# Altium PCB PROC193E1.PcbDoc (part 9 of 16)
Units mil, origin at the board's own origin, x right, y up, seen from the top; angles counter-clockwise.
Board outline 7700 x 2300 mil, 6 copper layers (Top Layer, GND 1, SIG 1, PWR, GND 2, Bottom Layer), stack 60.98 mil thick; 946 components, 667 nets, 9401 pads, 1730 vias.
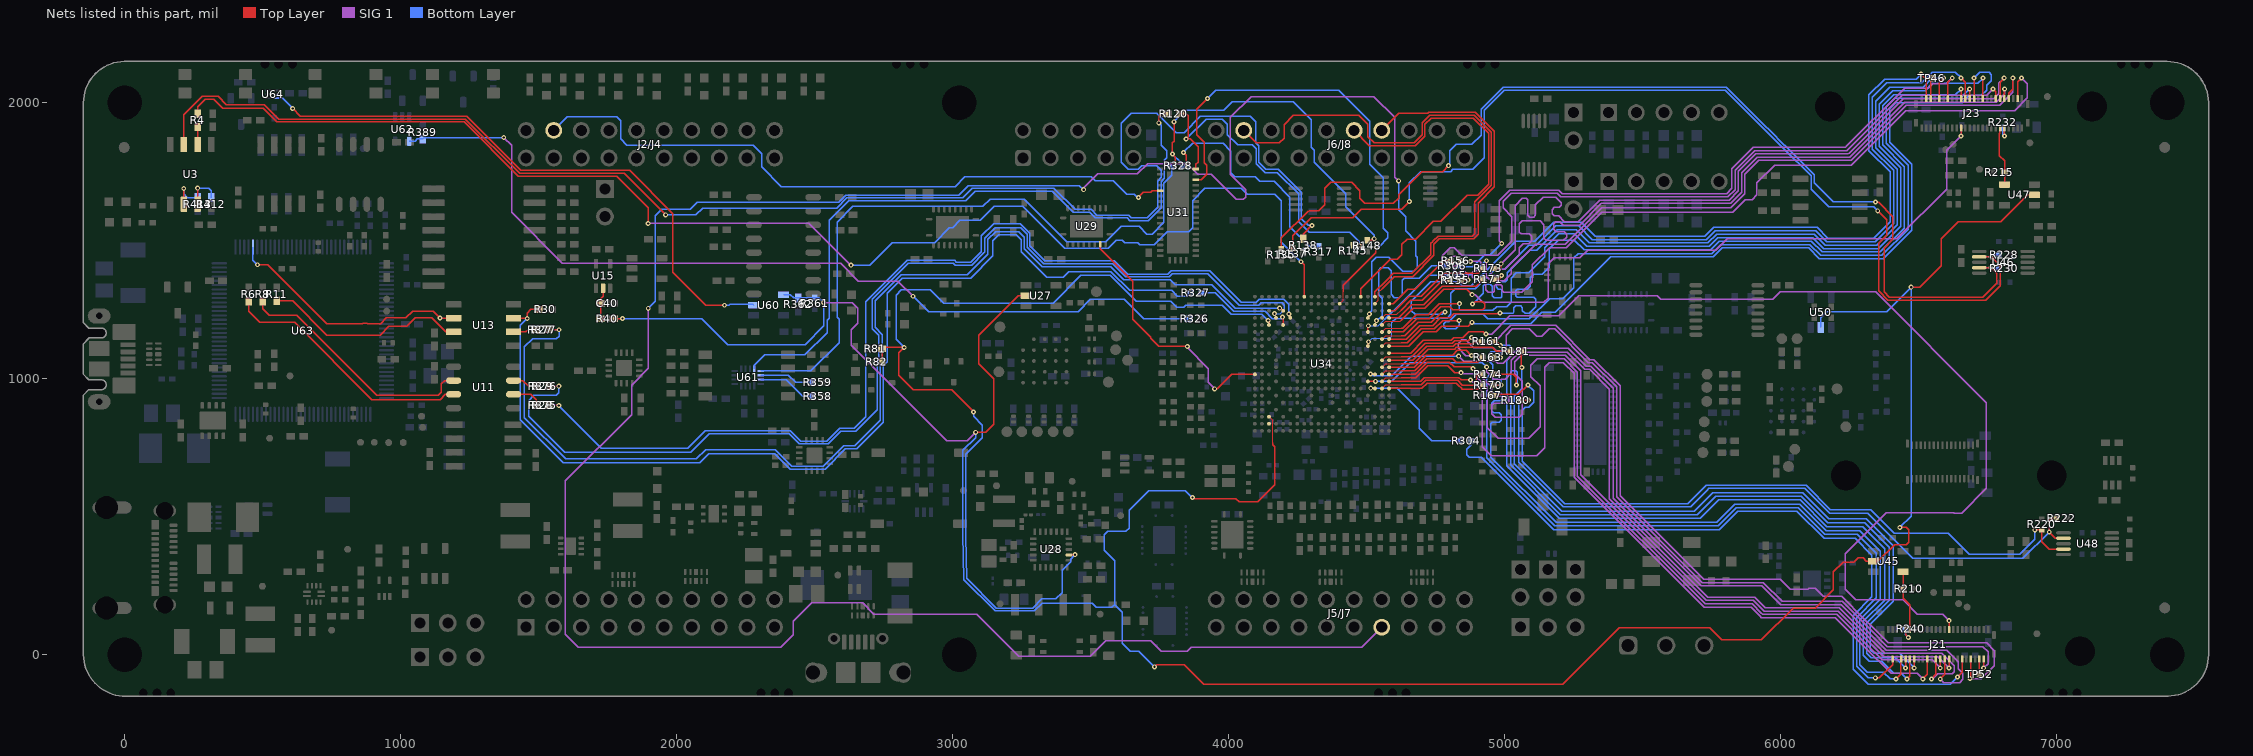
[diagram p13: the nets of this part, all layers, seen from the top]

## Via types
v1: diameter 18, hole 8, Top Layer to Bottom Layer, tented both sides, 1710 vias
v2: diameter 18, hole 8, Top Layer to Bottom Layer, tented top, 12 vias
v3: diameter 23.62, hole 11.81, Top Layer to Bottom Layer, tented both sides, 8 vias

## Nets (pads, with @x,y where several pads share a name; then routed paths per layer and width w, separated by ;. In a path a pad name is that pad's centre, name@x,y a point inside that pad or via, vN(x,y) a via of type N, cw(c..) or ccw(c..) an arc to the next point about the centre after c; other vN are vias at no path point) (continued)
AM261_PORZ: R40.1 R361.1 R362.2 U27.2 U34.V3 U45.2 U47.2 U50.2 U60.4 | length 10447.9
  Top Layer w3.94: U34.V3@4145.67,862.57 4158.46,849.77 4158.46,767.84
  Top Layer w5.3: R40.1@1771.58,1218.35 1802.65,1218.35 v1(1803,1218) ; v1(3082.87,805.99) 3119.32,805.99 3147.88,834.55 3147.88,999.75 3093.76,1053.86 3093.76,1157.29 3237.81,1301.34 U27.2@3265.34,1301.34 ; v1(3730.78,-43.56) 3738.78,-35.56 3837.83,-35.56 3909.6,-107.34 5209.97,-107.34 5415.31,98 5742.28,98 5786.59,53.69 5928.84,53.69 6044.31,169.16 6124.16,169.16 6190.05,235.05 6190.05,300.17 6225.81,335.93 6265.2,335.93 6280.07,350.8 6298.59,350.8 6310.21,339.18 6333.75,339.18 U45.2@6334.74,338.19 6352.07,338.19 6412.1,398.22 6454.99,398.22 6463.84,407.06 6463.84,452.86 6455.3,461.4 v1(6431.32,461.4) ; v1(3868.14,569.65) 3871.57,569.65 3875.52,565.7 4025.57,565.7 4037.48,553.79 4104.58,553.79 4166.63,615.85 4166.63,753.52 4158.46,761.69 4158.46,767.84 ; v1(6472.29,1331.83) 6503.84,1331.83 6581.9,1409.89 6581.9,1507.23 6643.76,1569.08 6797.08,1569.08 6894.33,1666.33 U47.2@6918.85,1666.33
  SIG 1 w4.75: v1(2531.83,1276.32) 2634.87,1276.32 2655.9,1255.29 2655.9,1202.1 2632.03,1178.24 2632.03,1121.49 2977.24,776.28 3053.16,776.28 v1(3082.87,805.99)
  Bottom Layer w5.3: v1(1803,1218) 2090.03,1218 2183.86,1124.17 2464.57,1124.17 2531.83,1191.43 v1(2531.83,1276.32) 2515.11,1293.03 R361.1@2499.12,1293.03 R362.2@2440.55,1293.03 ; U60.4@2386.73,1304.51 2411.53,1304.51 2423.11,1292.92 R362.2@2440.44,1292.92 ; v1(3082.87,805.99) 3082.87,786.59 3036.64,740.36 3036.64,436.49 3039.42,273.9 3039.83,273.5 3039.83,272.38 3153.21,159 3295.57,159 3323.62,187.05 3505.55,187.05 3520.07,172.53 3576.6,172.53 3586.29,182.21 ; v1(3730.78,-43.56) 3674.29,12.92 3673.48,13.74 3668.27,13.74 3643.2,13.74 3614.79,42.15 3614.79,153.71 3586.29,182.21 ; v1(3868.14,569.65) 3842.89,594.9 3709.67,594.9 3639.07,524.3 3639.07,459.27 3627.26,447.45 3561,447.45 3548.77,435.22 3548.77,378.35 3586.29,340.83 3586.29,182.21 ; U50.2@6145.52,1186.5 6145.52,1221.28 6167.38,1243.14 6280.78,1243.14 6383.6,1243.14 v1(6472.29,1331.83) 6472.29,502.36 v1(6431.32,461.4)
AM261_PORZ_PB: U60.2 U64.6 | length 2163.8
  Top Layer w5.3: v1(608.14,1979.7) 636.13,1951.71 1238.29,1951.71 1434.85,1755.15 1828.75,1755.15 1986.19,1597.71 1986.19,1386.39 2105.48,1267.1 2172.34,1267.1 v1(2173.02,1266.42)
  Bottom Layer w5.3: U64.6@551.18,2016.42 571.43,2016.42 v1(608.14,1979.7) ; v1(2173.02,1266.42) 2173.24,1266.65 2189.97,1266.65 2192.62,1269.3 2276.27,1269.3 U60.2@2278.46,1267.1
AM261_PORZ_RC: C40.1 R40.2 U15.2 | length 113.5
  Top Layer w5.3: R40.2@1724.33,1218.35 C40.1@1724.33,1273.35 1724.33,1290.39 1732.95,1299.01 U15.2@1732.95,1328.23
AM261_PR0_MDIO0_MDC: R180.1 R222.1 U48.2 | length 2572.6
  Top Layer w5.3: R180.1@5059.85,922.71 5085.48,922.71 v1(5085.72,922.47) ; R222.1@6997.71,495.49 6982.53,495.49 6972.59,485.56 v1(6972.59,444.64) 6994.75,422.48 7023.87,422.48 U48.2@7024.14,422.21
  Bottom Layer w5.3: v1(5085.72,922.47) 5057.99,922.47 5051.32,915.8 5051.32,697.51 5211.83,537 5674.6,537 5733.53,595.94 5733.53,596.93 5739.72,603.12 6085.95,603.12 6176.94,512.12 6315.27,512.12 6477.87,349.52 6877.48,349.52 v1(6972.59,444.64)
AM261_PR0_MDIO0_MDIO: R167.1 R220.1 U48.4 | length 2715.9
  Top Layer w5.3: R167.1@4957.22,941.07 4959.49,943.34 5049.51,943.34 v1(5083.64,977.48) ; v1(6920.45,451.78) 6920.94,452.27 R220.1@6945.06,452.27 6945.06,410.38 6972.59,382.84 U48.4@7024.14,382.84
  Bottom Layer w5.3: v1(5083.64,977.48) 5105.04,956.08 5105.04,915.26 5087.58,897.8 5074.56,897.8 5063.15,886.39 5063.15,701.47 5216.85,547.77 5663.44,547.77 5729.08,613.42 6091.94,613.42 6179.33,526.02 6325.46,526.02 6411.47,440.02 6606.22,440.02 6682.67,363.56 6864.98,363.56 6920.45,419.03 v1(6920.45,451.78)
AM261_PR1_MDIO0_MDC: R135.1 R230.1 U46.9 | length 3758.4
  Top Layer w5.3: R135.1@4190.71,1469.03 4190.71,1510.97 4287.64,1607.9 4290.7,1607.9 4291.26,1608.46 4297.13,1608.46 4297.23,1608.35 4313.4,1608.35 4313.51,1608.46 4325.99,1608.46 4348.04,1630.51 4348.04,1690.69 4368.59,1711.25 4444.8,1711.25 4474.68,1681.36 4474.68,1653.59 4493.01,1635.26 4595.87,1635.26 4615.01,1654.4 4615.01,1666.72 4699.18,1750.9 4774.65,1750.9 v1(4795.88,1772.13) ; v1(6343,1641) 6344.82,1639.18 6354.55,1639.18 6406,1587.74 6406,1504.81 6374.02,1472.83 6374.02,1315.35 6393.44,1295.93 6731.9,1295.93 6782.48,1346.51 6782.48,1382.23 v1(6761.95,1402.77) 6761.71,1402.53 U46.9@6719.18,1402.53
  Bottom Layer w5.3: v1(4795.88,1772.13) 4795.88,1775.57 4801.18,1780.86 4801.18,1826.01 4824.54,1849.38 4880.6,1849.38 4914.01,1882.8 4914.01,1976.18 4993.59,2055.76 5803.18,2055.76 5941.68,1917.26 5941.68,1917.13 5959.15,1899.66 5959.27,1899.66 6013.01,1845.92 6013.85,1845.92 6121.02,1738.75 6121.02,1709.71 6189.73,1641 v1(6343,1641) ; v1(6761.95,1402.77) 6764.39,1400.32 R230.1@6789.85,1400.32
AM261_PR1_MDIO0_MDIO: R137.1 R228.1 U46.7 | length 3715.2
  Top Layer w5.3: R137.1@4231.93,1473.63 4231.93,1517.49 4298.13,1583.7 4449.26,1583.7 4450.38,1584.81 4450.74,1584.81 4480.49,1614.56 4626.38,1614.56 v1(4654.17,1642.35) ; v1(6351.26,1608.66) 6383.48,1576.43 6383.48,1520.4 6354,1490.92 6354,1318.76 6387.43,1285.33 6743.24,1285.33 6795.1,1337.2 6795.1,1408.75 v1(6761.95,1441.9) U46.7@6719.18,1441.9
  Bottom Layer w5.3: v1(4654.17,1642.35) 4654.17,1709.91 4695.07,1750.81 4804.37,1750.81 4811.99,1758.43 4883.27,1758.43 4925.07,1800.23 4925.07,1972.24 4998.29,2045.46 5798.91,2045.46 5931.38,1912.99 5931.38,1912.87 5954.88,1889.36 5955.01,1889.36 6008.75,1835.62 6009.58,1835.62 6110.42,1734.78 6110.42,1686.81 6174.33,1622.91 6337.01,1622.91 v1(6351.26,1608.66) ; v1(6761.95,1441.9) 6768.79,1448.74 R228.1@6789.85,1448.74
AM261_RESETN_PB: R326.1 R389.1 U62.4 | length 3280
  SIG 1 w4.75: v1(1373,1874) 1401.47,1845.53 1401.47,1602.53 1585.46,1418.54 2593.61,1418.54 2658.32,1353.82 2801.38,1353.82 v1(2856.14,1299.07)
  Bottom Layer w5.3: U62.4@1030.59,1860.75 1052.07,1860.75 1060.28,1868.97 R389.1@1079.41,1868.97 1084.44,1874 v1(1373,1874) ; v1(2856.14,1299.07) 2896.75,1258.45 2912.45,1242.76 3453.97,1242.76 3498.78,1287.58 3621.16,1287.58 3691.51,1217.23 R326.1@3853.59,1217.23
AM261_RGMII1_INTn: J23.10 R232.1 | length 61.5
  Top Layer w5.3: v1(6810.42,1879.92) J23.10@6810.42,1908.44
  Bottom Layer w5.3: R232.1@6804.23,1910.3 6804.23,1886.1 v1(6810.42,1879.92)
AM261_RGMII1_RD0: J23.23 U34.H20 | length 3170.8
  Top Layer w5.3: U34.H20@4580.71,1118.47 4652.87,1118.47 4705.4,1170.99 4751.53,1170.99 4771.29,1190.76 4867.08,1190.76 v1(4881.08,1204.76) ; v1@6699.81,2089.31 6700.18,2088.94 J23.23@6700.18,2015.13
  Bottom Layer w5.3: v1(4881.08,1204.76) 4884.35,1204.76 4889.33,1199.78 5094,1199.78 5134.71,1240.49 5182.49,1240.49 5383.33,1441.33 5754.9,1441.33 5787.66,1474.09 6100.52,1474.09 6139.91,1434.7 6261.94,1434.7 6261.99,1434.65 6370.97,1434.65 6473.68,1537.35 6473.68,1778.03 6393.86,1857.85 6393.86,1979.1 6415.8,2001.04 6658.02,2001.04 6683.51,2026.54 6726.76,2026.54 6746.24,2046.02 6746.24,2062.97 6763.05,2079.78 6763.05,2102.24 6755.25,2110.04 6720.55,2110.04 v1@6699.81,2089.31
  other v1: 6699.81,2090
AM261_RGMII1_RD1: J23.25 U34.H19 | length 3184.2
  Top Layer w3.94: U34.H19@4555.12,1118.47 4567.91,1131.27 4624.25,1131.27
  Top Layer w5.3: 4624.25,1131.27 4647.16,1131.27 4697.48,1181.59 4745.06,1181.59 4774.3,1210.83 v1(4834.81,1210.83) ; J23.25@6684.43,2015.13 v1(6684.43,2050.04)
  Bottom Layer w5.3: v1(4834.81,1210.83) 4834.81,1193.96 4822.3,1181.45 4786.06,1181.45 4779,1188.5 4779,1200 4785.39,1206.39 4797.39,1206.39 4824.43,1233.43 4921.52,1233.43 4938.1,1216.85 5089.47,1216.85 5163.09,1290.46 5210.21,1290.46 5250.49,1330.75 5250.49,1438.49 5265.76,1453.76 5749.75,1453.76 5782.51,1486.51 6105.67,1486.51 6145.05,1447.12 6267.08,1447.12 6267.14,1447.07 6365.83,1447.07 6461.26,1542.5 6461.26,1772.89 6381.44,1852.71 6381.44,1984.78 6412.42,2015.77 6650.16,2015.77 v1(6684.43,2050.04)
AM261_RGMII1_RD2: J23.27 U34.H17 | length 3183.6
  Top Layer w5.3: U34.H17@4503.93,1118.47 4503.93,1132.35 v1(4505.78,1134.2) ; v1(6653,2090) 6668.69,2074.32 J23.27@6668.69,2015.13
  Bottom Layer w3.94: v1(4505.78,1134.2) 4519.01,1147.43 4584.02,1147.43 4591.3,1154.71 4591.3,1205.37
  Bottom Layer w5.3: 4591.3,1205.37 4605.99,1220.06 4791.38,1220.06 4804.75,1233.43 4804.75,1310.46 4819.72,1325.44 4892.1,1325.44 4962.91,1396.25 4999.25,1396.25 5086.24,1483.24 5114.24,1483.24 5184.93,1553.93 5268.07,1553.93 5317.38,1504.62 5730.33,1504.62 5761.92,1536.21 6126.25,1536.21 6165.64,1496.82 6342.34,1496.82 6408.94,1563.43 6408.94,1754.91 6331.74,1832.12 6331.74,2020.32 6383.69,2072.27 6510,2072.27 6548.92,2111.2 6631.8,2111.2 v1(6653,2090)
AM261_RGMII1_RD3: J23.29 U34.G20 | length 3183.5
  Top Layer w5.3: U34.G20@4580.71,1144.06 4642.99,1144.06 4692.01,1193.07 4739.02,1193.07 4766.95,1221.01 4769.91,1221.01 4770.04,1221.13 4801.64,1221.13 4815.41,1234.91 4972.93,1234.91 4973.55,1235.53 4979.95,1235.53 v1(4982.38,1237.96) ; J23.29@6652.94,2015.13 v1(6652.94,2050.04)
  Bottom Layer w5.3: v1(4982.38,1237.96) 4982.53,1237.81 5029.9,1237.81 5033,1240.91 5033,1258.06 5039.01,1264.08 5057.23,1264.08 5064,1257.31 5064,1247.18 5074.2,1236.98 5088.92,1236.98 5113,1261.06 5113,1287.69 5104.69,1296 5045,1296 5040.01,1300.99 5040.01,1318.65 5045.91,1324.54 5080.54,1324.54 5091.53,1335.53 5091.53,1366.53 5104,1379 5136,1379 5161.9,1404.9 5161.9,1471.9 5192.81,1502.81 5251.79,1502.81 5287.25,1467.35 5492.87,1467.35 5745.77,1467.35 5777.36,1498.94 6110.81,1498.94 6150.2,1459.55 6272.23,1459.55 6272.29,1459.5 6360.68,1459.5 6447.48,1546.29 6447.48,1769.09 6369.01,1847.56 6369.01,1989.93 6408.35,2029.27 6632.75,2029.27 6652.94,2049.45 v1(6652.94,2050.04)
AM261_RGMII1_RESETn: J23.12 R215.1 U47.4 | length 213.7
  Top Layer w5.3: J23.12@6794.67,1908.44 6793.97,1907.75 6793.97,1889.85 6791.77,1887.65 6791.77,1872.2 6791.96,1872.01 6791.96,1807.8 6810.6,1789.16 R215.1@6810.6,1749.22 U47.4@6810.6,1703.75
AM261_RGMII1_RX_CTL: J23.45 U34.G19 | length 3183.5
  Top Layer w3.94: U34.G19@4555.12,1144.06 4567.91,1156.86 4624.25,1156.86
  Top Layer w5.3: 4624.25,1156.86 4638.25,1156.86 4686.57,1205.18 4734.35,1205.18 4770.68,1241.52 v1(4783.61,1241.52) ; v1(6508.62,2104.04) 6526.95,2085.71 J23.45@6526.95,2015.13
  Bottom Layer w5.3: v1(4783.61,1241.52) 4781.92,1241.52 4774.16,1233.75 4674.89,1233.75 4661.86,1246.79 4661.86,1281.83 4732.02,1352 4831,1352 4845.02,1337.98 4878.98,1337.98 5040,1499 5108.98,1499 5177.98,1568 5276.13,1568 5327,1517.13 5725.26,1517.13 5756.78,1548.64 6131.4,1548.64 6170.79,1509.25 6337.19,1509.25 6396.52,1568.58 6396.52,1749.77 6319.31,1826.97 6319.31,2029.11 6376.2,2086 6490.59,2086 v1(6508.62,2104.04)
AM261_RGMII1_RXC: J23.19 U34.F19 | length 3173.7
  Top Layer w3.94: U34.F19@4555.12,1169.65 4567.91,1182.45 4624.25,1182.45
  Top Layer w5.3: 4624.25,1182.45 4630.49,1182.45 4679.86,1231.82 4722.18,1231.82 4762.38,1272.01 v1(4835.37,1272.01) ; J23.19@6731.68,2015.13 6731.68,2088.05 v1@6732.91,2089.29
  Bottom Layer w5.3: v1(4835.37,1272.01) 4835.37,1250.98 4838.47,1247.88 4956.88,1247.88 4970.21,1261.21 5006.69,1261.21 5022.54,1277.06 5022.54,1364.54 5041.82,1383.82 5086.04,1383.82 5145,1442.79 5145,1475 5195,1525 5252,1525 5297.23,1479.77 5487.72,1479.77 5740.62,1479.77 5772.22,1511.36 6115.96,1511.36 6155.35,1471.97 6277.38,1471.97 6277.43,1471.92 6352.57,1471.92 6433.79,1553.14 6433.79,1765.21 6356.59,1842.41 6356.59,1995.08 6405.51,2044 6522.97,2044 6549.08,2070.11 6713.74,2070.11 v1@6732.67,2089.05
  other v1: 6732.91,2090
AM261_RGMII1_RXLINK: J23.43 TP46.1 | length 75.9
  Top Layer w5.3: J23.43@6542.7,2015.13 6542.7,2084.44 TP46.1@6547.36,2089.1
AM261_RGMII1_TD0: J23.7 R305.1 | length 2564.5
  Top Layer w5.3: J23.7@6826.17,2015.13 6826.17,2035.17 6840.77,2049.77 v1(6840.77,2089.76)
  SIG 1 w4.75: v1(4933.45,1427.73) 4933.45,1370.66 4949.53,1354.58 4997.8,1354.58 5024.13,1380.92 5024.13,1400.13 5112,1488 5218.57,1488 5350.4,1619.83 5819.08,1619.83 5869.88,1670.62 5869.88,1741.3 5919.85,1791.28 6254.49,1791.28 6257.5,1794.29 6434.39,1971.19 6453.98,1990.77 6792.75,1990.77 6840.77,2038.8 v1(6840.77,2089.76)
  Bottom Layer w5.3: R305.1@4829.77,1374.48 4832.81,1377.52 4879.17,1377.52 4924.73,1423.09 4925.37,1423.09 4930.02,1427.73 v1(4933.45,1427.73)
AM261_RGMII1_TD0_R: R305.2 U34.F17 | length 383.6
  Top Layer w5.3: U34.F17@4503.93,1169.65 4503.93,1190.6 v1(4505.56,1192.22)
  Bottom Layer w3.94: v1(4505.56,1192.22) 4542.22,1192.22 4565.5,1215.5
  Bottom Layer w5.3: 4565.5,1215.5 4624.25,1274.25 4724.48,1374.48 R305.2@4790.4,1374.48
AM261_RGMII1_TD1: J23.9 R171.1 | length 2655.9
  Top Layer w5.3: R171.1@4959.95,1359.91 4978.3,1359.91 4987.57,1369.18 v1(4987.57,1374.48) ; J23.9@6810.42,2015.13 6810.42,2049.35 v1(6811.11,2050.04)
  SIG 1 w4.75: v1(4987.57,1374.48) 4956.52,1374.48 4950.64,1380.36 4950.64,1397.67 4956.14,1403.16 4969.84,1403.16 4975.5,1397.5 5000.5,1397.5 5053,1450 5053,1475.23 5066.77,1489 5087,1489 5098,1500 5098,1516 5089,1525 5059,1525 5053,1531 5053,1562 5063,1572 5128.99,1572 5142,1558.99 5142,1509.22 5150.05,1501.17 5211.89,1501.17 5224.31,1513.59 5224.31,1524.2 5216.03,1532.48 5187.16,1532.48 5178,1541.64 5178,1561.52 5185.18,1568.7 5199.3,1568.7 5211,1557 5270.78,1557 5348.5,1634.72 5348.88,1634.72 5349.45,1635.29 5386.85,1635.29 5450.61,1635.29 5817.75,1635.29 5858,1675.54 5858,1746.22 5914.93,1803.15 5955.99,1803.15 6249.57,1803.15 6252.58,1806.17 6434.39,1987.98 6449.06,2002.65 6781.02,2002.65 6811.11,2032.74 v1(6811.11,2050.04)
AM261_RGMII1_TD1_R: R171.2 U34.D20 | length 397.5
  Top Layer w5.3: U34.D20@4580.71,1220.83 4615.38,1220.83 4663.43,1268.88 4706.62,1268.88 4773.27,1335.52 4896.19,1335.52 R171.2@4920.58,1359.91
AM261_RGMII1_TD2: J23.11 R173.1 | length 2644.3
  Top Layer w5.3: R173.1@4960.18,1399.64 4979.94,1399.64 4986.77,1406.46 v1(4986.77,1416.83) ; J23.11@6794.67,2015.13 6794.67,2075.16 v1(6809.27,2089.76)
  SIG 1 w4.75: v1(4986.77,1416.83) 5037.71,1467.78 5037.71,1627.44 5063.84,1653.57 5078.04,1653.57 5083,1648.61 5083,1592.99 5089.99,1586 5104.32,1586 5111.19,1592.87 5111.19,1630.42 5138.94,1658.17 5185.06,1658.17 5204.84,1638.39 5204.84,1628.63 5196.93,1620.71 5179.84,1620.71 5171.1,1611.97 5171.1,1598.1 5179.19,1590 5195,1590 5215.67,1569.33 5266.31,1569.33 5343.58,1646.6 5343.96,1646.6 5344.53,1647.17 5381.93,1647.17 5455.53,1647.17 5812.83,1647.17 5846.13,1680.46 5846.13,1751.14 5910.01,1815.03 5960.91,1815.03 6244.65,1815.03 6247.66,1818.04 6434.39,2004.77 6444.14,2014.52 6771.86,2014.52 6789.89,2032.55 6789.89,2070.38 v1(6809.27,2089.76)
AM261_RGMII1_TD2_R: R173.2 U34.C20 | length 403.6
  Top Layer w5.3: U34.C20@4580.71,1246.42 4600.65,1246.42 4653.73,1299.5 4697.98,1299.5 4780.33,1381.85 4903.03,1381.85 R173.2@4920.81,1399.64
AM261_RGMII1_TD3: J23.13 R155.1 | length 2740.9
  Top Layer w5.3: R155.1@4839.51,1357.29 4866.29,1357.29 v1(4867,1358) ; v1(6769.25,2050.35) 6778.92,2040.68 J23.13@6778.92,2015.13
  SIG 1 w4.75: v1(4867,1358) 4866.88,1358.12 4866.88,1376.82 4850.23,1393.47 4841.12,1393.47 4832.34,1384.69 4823.51,1384.69 4813.05,1395.15 4813.05,1402.05 4834.04,1423.04 4834.04,1433 4823.04,1444 4812,1444 4793.04,1425.04 4782.04,1425.04 4773.57,1433.51 4773.57,1446.65 4802.14,1475.22 4816.78,1475.22 4844.67,1447.33 4974.06,1447.33 5025.83,1499.11 5025.83,1587.8 4994.06,1619.58 4994.06,1643.06 5023,1672 5190,1672 5202.96,1659.04 5377.01,1659.04 5460.45,1659.04 5807.91,1659.04 5834.25,1685.38 5834.25,1756.06 5905.09,1826.9 5965.83,1826.9 6239.73,1826.9 6242.75,1829.92 6434.39,2021.57 6439.28,2026.46 6745.35,2026.46 v1(6769.25,2050.35)
AM261_RGMII1_TD3_R: R155.2 U34.D19 | length 301.5
  Top Layer w3.94: U34.D19@4555.12,1220.83 4567.91,1233.63 4608.63,1233.63 4624.25,1249.25
  Top Layer w5.3: 4624.25,1249.25 4659.88,1284.88 4700.37,1284.88 4772.78,1357.29 R155.2@4800.14,1357.29
AM261_RGMII1_TX_CTL: J23.35 R306.1 | length 2312.8
  Top Layer w5.3: J23.35@6605.69,2015.13 6605.69,2074.01 v1@6621.15,2089.47
  SIG 1 w4.75: v1(4988.9,1490.44) 4988.9,1490.91 4979.96,1499.85 4979.96,1645.96 5018,1684 5141.8,1684 5141.92,1683.88 5194.92,1683.88 5207.58,1671.21 5803.29,1671.21 5822.38,1690.3 5822.38,1760.98 5900.18,1838.78 5970.75,1838.78 6234.81,1838.78 6237.83,1841.79 6434.39,2038.36 6449.06,2053.03 6534.34,2053.03 6550.48,2069.16 6600.31,2069.16 v1(6621.15,2090)
  Bottom Layer w5.3: R306.1@4829.77,1409.48 4833.49,1405.76 4883.87,1405.76 4926.71,1448.6 4947.06,1448.6 v1(4988.9,1490.44)
AM261_RGMII1_TX_CTL_R: R306.2 U34.E18 | length 637.7
  Top Layer w5.3: U34.E18@4529.52,1195.24 v1(4535.54,1210.46)
  Bottom Layer w5.3: v1(4535.54,1210.46) 4536.71,1210.46 4555.31,1229.06 4555.31,1291.11 4542.42,1304 4542.42,1348.43 4542.42,1393.32 4550.68,1401.59 4578.41,1401.59 4588,1392 4588,1305.91 4599.91,1294 4617,1294 4628,1305 4628,1356.28 4635.72,1364 4690.25,1364 4735.73,1409.48 R306.2@4790.4,1409.48
AM261_RGMII1_TXC: J23.3 R156.1 | length 2766.3
  Top Layer w5.3: R156.1@4842.45,1428.43 4872.07,1428.43 v1(4875.21,1425.28) ; J23.3@6857.87,2015.34 6857.87,2075.37 6858.2,2075.7 v1(6872.26,2089.76)
  SIG 1 w4.75: v1(4875.21,1425.28) 4908.72,1425.28 4916.87,1417.13 4916.87,1397.58 4910.28,1391 4889.23,1391 4882.63,1384.4 4882.63,1370.52 4890,1363.16 4922.4,1363.16 4930.75,1354.81 4930.75,1322.41 4940.38,1312.78 4957.78,1312.78 4962,1317 4962,1336.27 4967.12,1341.39 4985.55,1341.39 4991,1335.93 4991,1318.43 4996.65,1312.78 5061.41,1312.78 5099.98,1351.35 5099.98,1412.89 5162.09,1475 5222.36,1475 5350.73,1603.37 5825.42,1603.37 5870.71,1648.65 5896.33,1648.65 5913.75,1666.08 5913.75,1710.9 5977.31,1774.46 6255.02,1774.46 6434.39,1953.84 6452.6,1972.04 6847.52,1972.04 6893.12,2017.64 6893.12,2068.91 v1(6872.26,2089.76)
AM261_RGMII1_TXC_R: R156.2 U34.B20 | length 287.2
  Top Layer w5.3: U34.B20@4580.71,1272.01 4596.26,1272.01 4648.73,1324.48 4674.86,1324.48 4778.81,1428.43 R156.2@4803.08,1428.43
AM261_RGMII2_INTn: J21.10 R240.1 | length 68.9
  Top Layer w5.3: J21.10@6452.05,91.39 6452.05,73 v1(6462.05,63)
  Bottom Layer w5.3: R240.1@6451.15,94.86 6451.15,73.9 v1(6462.05,63)
AM261_RGMII2_RD0: J21.23 U34.N17 | length 3150.9
  Top Layer w5.3: U34.N17@4503.93,990.52 4504.19,990.77 4531.32,990.77 v1(4531.57,991.02) ; v1@6546.18,-86.1 6561.9,-70.38 6561.9,-15.69 J21.23@6562.29,-15.3
  SIG 1 w4.75: v1(4934.45,1042.98) 4934.45,1024.8 4960.26,999 5001.15,999 5024.24,1022.09 5024.24,1067.19 5054.06,1097 5227.13,1097 5289.85,1034.28 5307.34,1034.28 5379,962.62 5379,565.07 5734.92,209.16 5905.08,209.16 5944.35,169.88 6212.56,169.88 6213.51,168.93 6317.96,64.49 6377.22,5.23 6583.55,5.23 6628.45,-39.66 6628.45,-61.49 6621.99,-67.94 6569.01,-67.94 6549.76,-87.19 v1(6546.18,-87.19)
  Bottom Layer w5.3: v1(4531.57,991.02) 4590.16,991.02 4657.6,1058.47 4918.96,1058.47 v1(4934.45,1042.98)
AM261_RGMII2_RD1: J21.25 U34.N19 | length 3255.1
  Top Layer w3.94: U34.N19@4555.12,990.52 4567.91,1003.31 4623.54,1003.31 4623.63,1003.22 4624.25,1003.22
  Top Layer w5.3: 4624.25,1003.22 4676.63,1003.22 4719.99,1046.58 4793.42,1046.58 4817.89,1022.11 v1(4841.82,1022.11) ; v1@6578.04,-47.3 J21.25@6578.04,-15.3
  Top Layer w8: v1(6577.7,-47.64) v1@6578.04,-47.3
  SIG 1 w4.75: v1(4841.82,1022.11) 4845.41,1022.11 4849.36,1018.16 4885.84,1018.16 4937,967 4937,823 4976,784 5086,784 5127.83,825.83 5127.83,974.35 5094,1008.18 5094,1049.71 5117,1072.71 5214.94,1072.71 5263.07,1024.58 5263.07,647.42 5726.28,184.2 5896.45,184.2 5929.79,150.86 5934.52,146.13 5984.69,146.13 6202.72,146.13 6203.68,145.18 6308.12,40.74 6367.38,-18.52 6548.59,-18.52 v1(6577.7,-47.64)
AM261_RGMII2_RD2: J21.27 U34.M18 | length 3156.1
  Top Layer w5.3: v1(4513.35,1017.16) 4513.87,1016.63 4529,1016.63 U34.M18@4529.52,1016.11 ; v1@6577.67,-86.1 6593.33,-70.44 6593.33,-54.13 ; 6593.35,-54.12 6593.35,-41.15 6593.33,-15.75 J21.27@6593.79,-15.3
  SIG 1 w4.75: v1(4833,1082) 4850.92,1064.08 4966.97,1064.08 4974.74,1056.3 4994.73,1056.3 5048.7,1110.28 5230.65,1110.28 5294.77,1046.16 5312.25,1046.16 5392.96,965.46 5392.96,567.91 5711.37,249.5 5931.71,249.5 5999.45,181.76 6217.48,181.76 6218.43,180.81 6322.88,76.36 6382.13,17.1 6601.9,17.1 6643.28,-24.28 6643.28,-50.22 6659.97,-66.91 6659.97,-89.47 6648.73,-100.72 6591.2,-100.72 v1(6577.67,-87.19)
  Bottom Layer w5.3: v1(4513.35,1017.16) 4516.79,1017.16 4522.49,1011.45 4589.85,1011.45 4660.4,1082 v1(4833,1082)
AM261_RGMII2_RD3: J21.29 U34.M20 | length 3256.6
  Top Layer w5.3: U34.M20@4580.71,1016.11 4674.95,1016.11 4719.31,1060.47 4799.58,1060.47 4816.82,1043.23 4876.04,1043.23 4881.54,1037.73 v1(4884.98,1037.73) ; v1@6609.53,-47.3 J21.29@6609.53,-15.3
  Top Layer w8: v1(6609.2,-47.64) v1@6609.53,-47.3
  SIG 1 w4.75: v1(4884.98,1037.73) 4953,969.71 4953,946 4963,936 5010,936 5015,931 5015,917 5009,911 4960,911 4953,904 4953,873 4965,861 5052,861 5063,872 5063,991.22 5036.76,1017.47 5036.76,1061.1 5060.24,1084.58 5219.86,1084.58 5274.94,1029.5 5274.94,652.34 5730.32,196.96 5900.49,196.96 5934.71,162.74 5939.43,158.01 5989.61,158.01 6207.64,158.01 6208.6,157.06 6313.04,52.61 6372.3,-6.65 6568.21,-6.65 v1(6609.2,-47.64)
AM261_RGMII2_RESETn: J21.12 R210.1 U45.4 | length 219.7
  Top Layer w5.3: U45.4@6443,300.79 R210.1@6443,239.5 6443,205.39 6467.8,180.59 J21.12@6467.8,91.39
AM261_RGMII2_RX_CTL: J21.45 U34.L20 | length 3243.5
  Top Layer w5.3: U34.L20@4580.71,1041.7 4671.41,1041.7 4715.61,1085.9 4810.52,1085.9 4827.35,1102.72 4860.44,1102.72 v1(4878.89,1084.27) ; v1@6735.52,-47.3 J21.45@6735.52,-15.3
  Top Layer w8: v1(6735.18,-47.64) v1@6735.52,-47.3
  SIG 1 w4.75: v1(4878.89,1084.27) 4859.07,1084.27 4831.1,1112.25 4831.1,1127.09 4844.88,1140.88 4858.88,1140.88 4887.75,1112 4958.48,1112 4969,1101.48 4992.49,1101.48 5004.51,1113.49 5004.51,1158.43 5026.62,1180.54 5088.73,1180.54 5115.25,1154.03 5134.32,1154.03 5160.8,1180.51 5180.26,1180.51 5302.73,1058.03 5317.17,1058.03 5404.83,970.38 5404.83,572.83 5716.29,261.37 5936.63,261.37 6004.37,193.63 6222.4,193.63 6327.79,88.24 6386.24,29.79 6732.43,29.79 6751.11,11.11 6751.11,-31.71 v1(6735.18,-47.64)
AM261_RGMII2_RXC: J21.19 U34.N20 | length 3257.6
  Top Layer w5.3: U34.N20@4580.71,990.52 4694.85,990.52 4709.03,1004.7 4833.15,1004.7 4841.71,996.14 v1(4876.25,996.14) ; v1@6514.68,-86.1 6530.4,-70.39 6530.4,-15.7 J21.19@6530.79,-15.3
  SIG 1 w4.75: v1(4876.25,996.14) 4918.3,954.09 4918.3,754.7 4951,722 5116,722 5144,750 5144,1041.98 5161.04,1059.02 5211.84,1059.02 5251.19,1019.66 5251.19,642.5 5721.89,171.81 5892.05,171.81 5924.87,138.99 5929.6,134.26 5979.77,134.26 6197.8,134.26 6303.2,28.86 6399.74,-67.68 6495.17,-67.68 v1(6514.68,-87.19)
AM261_RGMII2_RXLINK: J21.43 TP52.1 | length 54.1
  Top Layer w5.3: TP52.1@6719.47,-69.7 J21.43@6719.47,-15.6
AM261_RGMII2_TD0: J21.7 R170.1 | length 2754.3
  Top Layer w5.3: R170.1@4959.55,977.47 4986.77,977.47 v1(4986.85,977.38) ; v1(6417.81,-87.19) 6434.92,-70.09 6434.92,-16.69 J21.7@6436.31,-15.3
  Bottom Layer w5.3: v1(4986.85,977.38) 4986.85,991.15 4979.49,998.51 4959.19,998.51 4949.66,988.99 4949.66,957.34 4957,950 4982.81,950 4990,942.81 4990,926 4984,920 4961.48,920 4953.5,912.02 4953.5,882.81 4959.31,877 4979.54,877 4987,869.54 4987,849.61 4980.39,843 4954.66,843 4949.66,838 4949.66,715.98 5185.63,480.02 5768.81,480.02 5833.99,545.19 6068.67,545.19 6164.24,449.62 6286.04,449.62 6360.81,374.85 6360.81,201.06 6286.84,127.09 6286.84,-35.83 6313.43,-62.43 6370.89,-62.43 6395.65,-87.19 v1(6417.81,-87.19)
AM261_RGMII2_TD0_R: R170.2 U34.P20 | length 362.6
  Top Layer w5.3: U34.P20@4580.71,964.93 4699.68,964.93 4718.85,984.1 4824.62,984.1 4833.47,975.25 4841.53,967.19 4841.81,967.19 4846.5,962.51 4905.23,962.51 R170.2@4920.18,977.47
AM261_RGMII2_TD1: J21.9 R174.1 | length 2689.8
  Top Layer w5.3: R174.1@4960.18,1015.72 5031.28,1015.72 5041.94,1005.06 v1(5041.94,977.15) ; v1@6452.05,-47.3 J21.9@6452.05,-15.3
  Top Layer w8: v1(6451.72,-47.64) v1@6452.05,-47.3
  Bottom Layer w5.3: v1(5041.94,977.15) 5044.37,979.58 5044.37,1023.63 5039.02,1028.98 5025.98,1028.98 5020.95,1023.95 5020.95,687.82 5201.28,507.5 5691.09,507.5 5691.25,507.66 5696.72,507.66 5751.46,562.4 5751.56,562.4 5763.95,574.79 6074.22,574.79 6169.75,479.26 6303.5,479.26 6393.36,389.39 6393.36,197.5 6311.69,115.83 6311.69,4.92 6327.15,-10.54 6414.62,-10.54 v1(6451.72,-47.64)
AM261_RGMII2_TD1_R: R174.2 U34.P19 | length 411.7
  Top Layer w3.94: U34.P19@4555.12,964.93 4567.91,977.72 4624.25,977.72
  Top Layer w5.3: 4624.25,977.72 4697.72,977.72 4714.4,994.4 4828.88,994.4 4845.79,977.49 4885.34,977.49 4896.5,988.66 4896.5,1007.3 4904.92,1015.72 R174.2@4920.81,1015.72
AM261_RGMII2_TD2: J21.11 R161.1 | length 2752.4
  Top Layer w5.3: R161.1@4955.05,1135.18 4956.68,1133.54 4971.7,1133.54 v1(4984.52,1120.73) ; v1(6457.15,-87.19) 6467.52,-76.82 J21.11@6467.52,-15.58
  Bottom Layer w5.3: v1(4984.52,1120.73) 5015.27,1120.73 5027.61,1108.39 5027.61,1088.61 5006.88,1067.88 5006.88,684.32 5197.15,494.05 5707.72,494.05 5774.84,561.17 6070.27,561.17 6167.34,464.09 6296.4,464.09 6375.97,384.52 6375.97,197.98 6299.26,121.28 6299.26,-1.76 6303.2,-5.7 6320.47,-22.97 6365.17,-22.97 6409.15,-66.95 6436.91,-66.95 v1(6457.15,-87.19)
AM261_RGMII2_TD2_R: R161.2 U34.K20 | length 363.1
  Top Layer w5.3: U34.K20@4580.71,1067.29 4666.18,1067.29 4717.11,1118.22 4813.72,1118.22 4822.19,1126.7 4883.43,1126.7 4891.92,1135.18 R161.2@4915.68,1135.18
AM261_RGMII2_TD3: J21.13 R181.1 | length 2603.1
  Top Layer w5.3: R181.1@5059.85,1100.6 5059.85,1042.36 v1(5061.73,1040.49) ; v1@6483.55,-47.3 J21.13@6483.55,-15.3
  Top Layer w8: v1(6483.21,-47.64) v1@6483.55,-47.3
  Bottom Layer w5.3: v1(5061.73,1040.49) 5061.73,964.67 5038.89,941.83 5038.89,941.57 5034.36,937.04 5034.36,691.98 5206.42,519.92 5685.94,519.92 5753.24,587.22 6079.36,587.22 6173.42,493.16 6309.55,493.16 6408.01,394.7 6408.01,194.33 6324.11,110.44 6324.11,18.67 6337.8,4.99 6430.59,4.99 v1(6483.21,-47.64)
AM261_RGMII2_TD3_R: R181.2 U34.L19 | length 500.7
  Top Layer w3.94: U34.L19@4555.12,1041.7 4567.91,1054.49 4618.87,1054.49 4618.96,1054.41 4624.25,1054.41
  Top Layer w5.3: 4624.25,1054.41 4669.55,1054.41 4711.34,1096.2 4711.71,1096.2 4723.43,1107.93 4817.98,1107.93 4824.03,1113.97 4955.03,1113.97 4968.77,1100.23 R181.2@5020.12,1100.23
AM261_RGMII2_TX_CTL: J21.35 R304.1 | length 2658.1
  Top Layer w5.3: v1(6639.84,-80.81) 6656.78,-63.88 6656.78,-54.36 6656.54,-54.12 6656.54,-41.15 6656.78,-40.91 J21.35@6656.78,-15.3
  Bottom Layer w5.3: R304.1@4879.21,775.15 4878.46,774.39 4878.46,760.46 4862.26,744.26 4862.26,724.74 4870.51,716.49 4914.01,716.49 5177.5,453 5776.94,453 5844.28,520.34 6058.38,520.34 6156.6,422.12 6268.97,422.12 6330.11,360.98 6330.11,209.86 6261.99,141.74 6261.99,-53.22 6316.02,-107.25 6613.4,-107.25 v1(6639.84,-80.81)
AM261_RGMII2_TX_CTL_R: R304.2 U34.P18 | length 458.2
  Top Layer w5.3: v1(4514.3,965.82) 4515.2,964.93 U34.P18@4529.52,964.93
  Bottom Layer w5.3: v1(4514.3,965.82) 4596.56,965.82 4610.33,965.82 4690.93,885.23 4690.93,820.18 4735.96,775.15 R304.2@4839.84,775.15
AM261_RGMII2_TXC: J21.3 R163.1 | length 2714.7
  Top Layer w5.3: R163.1@4957.22,1077.65 4984.43,1077.65 v1(4984.52,1077.56) ; v1(6342.31,-83.37) 6357.03,-83.37 6404.81,-35.58 J21.3@6404.81,-15.3
  Bottom Layer w5.3: v1(4984.52,1077.56) 4984.52,1092.34 4978.54,1098.32 4950.97,1098.32 4942.96,1090.31 4942.96,1064.04 4956,1051 4956,1026 4934.24,1004.24 4934.24,713.84 5180.52,467.55 5773.91,467.55 5839.13,532.77 6063.52,532.77 6160.06,436.23 6276.52,436.23 6345.27,367.49 6345.27,205.88 6274.41,135.02 6274.41,-40.98 6316.8,-83.37 v1(6342.31,-83.37)
AM261_RGMII2_TXC_R: R163.2 U34.M19 | length 399.9
  Top Layer w3.94: U34.M19@4555.12,1016.11 4567.91,1028.9 4624.25,1028.9
  Top Layer w5.3: 4624.25,1028.9 4673.18,1028.9 4717.09,1072.82 4810.63,1072.82 4823.51,1059.94 4901.14,1059.94 R163.2@4918.86,1077.65
AM261_RMII1_CRS_DV/MII1_CRS: J23.30 U34.E19 | length 2605.7
  Top Layer w3.94: U34.E19@4555.12,1195.24 4567.91,1208.04 4620.83,1208.04 4624.25,1211.46
  Top Layer w5.3: 4624.25,1211.46 4668.77,1255.98 4710.22,1255.98 4779.47,1325.22 4861.3,1325.22 v1(4881.77,1304.75) ; v1(6652.94,1879.92) J23.30@6652.94,1908.44
  SIG 1 w4.75: v1(4881.77,1304.75) 4892.8,1304.75 4920.42,1277.14 5141.57,1277.14 5156.68,1292.25 5156.68,1417.43 5178.49,1439.24 5272.44,1439.24 5299.78,1466.59 5764.88,1466.59 5805.23,1506.94 6420.89,1506.94 6601.53,1687.58 6601.53,1828.52 v1(6652.94,1879.92)
AM261_RMII1_RX_ER/MII1_RX_ER: J23.39 U34.F20 | length 3182.9
  Top Layer w5.3: U34.F20@4580.71,1169.65 4632.8,1169.65 4681.23,1218.08 4725.43,1218.08 4768.39,1261.04 4800.78,1261.04 4811.91,1249.91 4920.53,1249.91 4928,1257.37 4928,1272.55 4920.55,1280 4892.72,1280 v1(4883.27,1270.62) v1(4883.27,1270.62) ; J23.39@6574.48,2015.42 6574.48,2072.07 6574.48,2073.58 v1@6590.01,2089.11
  Bottom Layer w5.3: v1(4883.27,1270.62) 4922,1309.35 4922,1336.25 4928.77,1343.01 4947.56,1343.01 4955,1335.57 4955,1301.56 4962.56,1294 4986.07,1294 4989.18,1297.1 4989.18,1321.9 4986.07,1325 4976.36,1325 4968.53,1332.84 4968.53,1345.53 4975,1352 5001,1352 5008.64,1359.64 5008.64,1383.64 5091,1466 5116.26,1466 5190.02,1539.76 5259.24,1539.76 5306.8,1492.2 5735.48,1492.2 5767.07,1523.79 6121.11,1523.79 6160.49,1484.4 6347.48,1484.4 6421.37,1558.29 6421.37,1760.06 6344.16,1837.27 6344.16,2006.33 6394.92,2057.08 6515.59,2057.08 6547.62,2089.11 v1@6590.01,2089.11
  other v1: 6590.01,2090
AM261_RMII2_CRS_DV/MII2_CRS: J21.30 U34.J20 | length 3946.2
  Top Layer w5.3: U34.J20@4580.71,1092.88 4658.81,1092.88 4704.75,1138.82 4805.18,1138.82 4815.36,1149 4847.3,1149 4869.33,1171.03 4922.05,1171.03 4930.85,1162.23 v1(4931.51,1162.23) ; J21.30@6609.53,91.39 v1@6609.53,123.39
  Top Layer w8: v1@6609.53,123.39 v1(6609.87,123.73)
  SIG 1 w4.75: v1(4931.51,1162.23) 4951.91,1162.23 5018.74,1229.07 5196.01,1229.07 5268.7,1301.75 5552.15,1301.75 5565.89,1288.02 5969.93,1288.02 5997.19,1315.28 6343.65,1315.28 6744.81,914.12 6744.81,602.95 6655.05,513.19 6627.97,513.19 6627.35,513.81 6382.08,513.81 6233.91,365.63 6233.91,236.59 6271.47,199.03 6443,199.03 6494.96,147.08 6586.53,147.08 v1(6609.87,123.73)
AM261_RMII2_RX_ER/MII2_RX_ER: J21.39 U34.K19 | length 3247.2
  Top Layer w3.94: U34.K19@4555.12,1067.29 4567.91,1080.09 4624.25,1080.09
  Top Layer w5.3: 4624.25,1080.09 4662.95,1080.09 4711.39,1128.53 4809.45,1128.53 4818.5,1137.57 4866.89,1137.57 v1(4879.08,1149.76) ; v1(6685.41,-86.1) 6687.84,-83.68 6687.84,-15.73 J21.39@6688.27,-15.3
  SIG 1 w4.75: v1(4879.08,1149.76) 4902.85,1125.99 4954.25,1125.99 5021.85,1193.59 5184.03,1193.59 5307.71,1069.91 5322.09,1069.91 5418,974 5418,576.45 5721.21,273.25 5998.35,273.25 6033.97,237.62 6098.79,237.62 6101.57,240.4 6124.64,240.4 6153.03,212.02 6220.81,212.02 6303.2,129.62 6332.71,100.11 6389.94,42.88 6745.65,42.88 6773,15.54 6773,-39.96
  SIG 1 w5.3: v1(6685.41,-86.1) 6726.86,-86.1 6773,-39.96
AM261_SAFETY_ERRORN: R81.1 R82.1 U28.21 U34.E3 | length 3511.3
  Top Layer w5.3: R82.1@2744.71,1061.57 2744.71,1106.46 R81.1@2742.9,1108.27 2748.39,1113.75 v1@2823.67,1113.75 ; v1(2823.83,1113.91) v1@2823.67,1113.75 ; v1(3075.44,879.77) 3075.44,881.22 2996.25,960.41 2856.59,960.41 2804.39,1012.61 2804.39,1094.47 v1@2823.67,1113.75 ; U28.21@3420.91,361.86 3442.67,361.86 v1(3442.67,362.75) ; v1(4142.84,1210.99) 4145.67,1208.17 U34.E3@4145.67,1195.24
  Bottom Layer w5.3: v1(2823.83,1113.91) 2795.12,1142.62 2795.12,1303.56 2813.98,1322.41 2918.6,1322.41 2967.5,1273.52 3363.09,1273.52 3464.21,1374.64 3570.41,1374.64 3664.54,1280.51 3789.68,1280.51 3810.68,1259.51 3820.44,1259.51 3820.51,1259.44 3835.96,1259.44 3843.48,1266.96 3976.65,1266.96 4009.31,1234.3 4119.53,1234.3 v1(4142.84,1210.99) ; 3050.11,277.78 3047.33,428.1 3047.33,726.47 3107.16,786.3 3107.16,832.18 3075.44,863.9 v1(3075.44,879.77) ; 3050.13,277.76 3050.13,276.65 3157.48,169.3 3288.98,169.3 3321.92,202.24 3373.55,202.24 3396.49,225.17 3396.49,306.11 3426.82,336.44 3426.82,346.9 v1(3442.67,362.75)
AM261_SOP0: R358.2 U61.15 | length 208.1
  Bottom Layer w5.3: U61.15@2304.25,997.28 2396.72,997.28 2457.12,936.88 R358.2@2487.31,936.88
AM261_SOP1: R359.2 U61.14 | length 193.9
  Bottom Layer w5.3: U61.14@2304.25,1013.03 2403.97,1013.03 2430.12,986.88 R359.2@2487.31,986.88
AM261_SOP2: R328.2 U61.13 | length 2317.7
  Bottom Layer w5.3: U61.13@2304.25,1028.77 2486.19,1028.77 2588.56,1131.15 2588.56,1215.38 2581.45,1222.49 2581.45,1568.05 2637.85,1624.44 3109.13,1624.44 3135.42,1650.73 3258.27,1650.73 3413,1496 3554,1496 3610.33,1552.33 3647.72,1552.33 3647.91,1552.52 3664.09,1552.52 3664.28,1552.33 3674.72,1552.33 3702.66,1524.4 3723.26,1524.4 3765.2,1566.34 3765.2,1709.22 3793.08,1737.1 R328.2@3793.08,1771.42
AM261_SOP3: R120.2 U61.12 | length 2429.7
  Top Layer w5.3: v1(3746.46,1927.53) 3746.46,1949 3755.78,1958.33 3773.78,1958.33 R120.2@3776.38,1960.93
  Bottom Layer w5.3: U61.12@2280.62,1036.65 2280.62,1049.59 2317.92,1086.88 2463.69,1086.88 2544.54,1167.73 2544.54,1211.75 2552.35,1219.56 2552.35,1574.75 2622.65,1645.04 3047.04,1645.04 3080.88,1678.88 3359.9,1678.88 3435.58,1603.2 3496.81,1603.2 3517.02,1582.99 3631.69,1582.99 3641.15,1573.53 3708.7,1573.53 3754.6,1619.43 3754.6,1698.46 3754.52,1698.54 3754.52,1713.53 3766.8,1725.81 3766.8,1791.96 3776.02,1801.18 3776.02,1825.42 3754.6,1846.85 3754.6,1918.08 3746.46,1926.22 v1(3746.46,1927.53)
AM261_SPI0_CLK: R148.1 R328.1 U31.41 | length 1334.9
  Top Layer w5.3: v1(3801,1931) 3801.64,1930.36 3801.64,1861.09 3795.55,1855 v1(3795.55,1814.06) 3806.24,1803.36 U31.41@3806.24,1776.2 ; R148.1@4502.07,1502 4518.25,1502 4523.36,1507.11 v1(4526.8,1507.11)
  Bottom Layer w5.3: v1(3795.55,1814.06) 3827.23,1782.37 3827.23,1780.58 3838.89,1768.93 R328.1@3840.32,1768.93 ; v1(3801,1931) 3842.84,1972.84 3981.52,1972.84 4013.04,2004.35 4233.29,2004.35 4298.27,1939.37 4298.27,1839.17 4309.24,1828.2 4309.24,1784.16 4423.42,1669.97 4423.42,1623.22 4526.8,1519.85 v1(4526.8,1507.11)
AM261_SPI0_CS0: U31.36 U34.B13 | length 1765.4
  Top Layer w3.94: U34.B13@4401.57,1272.01 4414.37,1284.81 4414.37,1315.32
  Top Layer w5.3: U31.36@3881.04,1721.09 3899.65,1721.09 3920.06,1741.5 3920.06,1773.86 3911.91,1782 3911.91,1856.89 3883.76,1885.04 3883.76,1976.46 v1(3923.19,2015.88) ; 4414.37,1315.32 4414.37,1338.39 4532.97,1457 v1(4532.97,1477.33)
  Bottom Layer w5.3: v1(3923.19,2015.88) 3952.85,2045.55 4397.55,2045.55 4510.19,1932.92 4510.19,1777.64 4559.36,1728.46 4559.36,1546.2 4576.19,1529.37 4576.19,1510.91 4544.48,1479.2 4534.84,1479.2 v1(4532.97,1477.33)
AM261_SPI0_CS0/PR1_PRU1_GPIO3: J2/J4.19 U31.5 | length 2443.8
  Top Layer w5.3: v1(3672.46,1657.28) 3690.34,1675.15 3716.5,1675.15 3723.06,1681.72 U31.5@3751.12,1681.72
  Bottom Layer w5.3: J2/J4.19@1554.17,1900 1603.51,1949.33 1781.91,1949.33 1796.54,1934.7 1796.54,1868.88 1818.97,1846.44 2276.91,1846.44 2307.55,1815.8 2307.55,1767.84 2378.85,1696.54 3008.33,1696.54 3042.98,1731.19 3501.77,1731.19 3515.42,1717.55 3580.85,1717.55 3630.22,1668.18 3658.13,1668.18 3669.02,1657.28 v1(3672.46,1657.28)
AM261_SPI0_D0: R120.1 R145.1 U31.38 | length 1250.2
  Top Layer w5.3: R120.1@3823.62,1960.93 3846.07,1960.93 3853.57,1953.43 3853.57,1876.92 v1(3845.65,1869) 3861,1869 3889.26,1840.74 3889.26,1784.83 3881.04,1776.61 U31.38@3881.04,1760.46 ; R145.1@4450.05,1483.49 v1(4473.15,1483.49)
  Bottom Layer w5.3: v1(3845.65,1869) 3917.69,1941.04 3976.69,1941.04 3995.21,1922.52 3995.21,1885.05 4031.89,1848.36 4084.62,1848.36 4098.71,1834.28 4098.71,1779.77 4131.35,1747.13 4176.36,1747.13 4252.87,1670.63 4252.87,1568.82 4291.4,1530.29 4438.18,1530.29 4472.38,1496.09 4472.38,1484.27 v1(4473.15,1483.49)
AM261_SPI0_D1: R317.1 U31.39 | length 815.7
  Top Layer w5.3: v1(3835.68,1820.3) 3836.18,1820.3 3845.63,1810.84 U31.39@3845.61,1776.2
  Bottom Layer w5.3: v1(3835.68,1820.3) 3868.55,1853.17 3973.6,1853.17 3979.47,1853.17 4005.51,1827.13 4007.04,1825.6 4007.04,1746.36 4021.5,1731.9 4064.72,1731.9 4096.45,1731.9 4113.04,1715.32 4164.46,1715.32 4221.55,1658.23 4221.55,1551.62 4292.99,1480.18 R317.1@4325.9,1480.18
AM261_SPI2_CLK: J5/J7.47 U34.D17 | length 9125.9
  Top Layer w4.75: U34.D17@4503.93,1220.83 4509.06,1225.96 4509.06,1231.51 v1(4509.06,1235.1)
  SIG 1 w4.75: v1(1896.53,1255.29) 1896.53,1037.57 1835.92,976.95 1835.92,869.34 1596.36,629.79 1596.36,73.89 1643.08,27.16 2376.6,27.16 2422.47,73.04 2422.47,122.35 2488.14,188.02 2674.04,188.02 2714.31,147.75 3086.9,147.75 3239.02,-4.37 3498,-4.37 3554.08,51.7 3717.26,51.7 3756.05,12.92 3849.46,12.92 3863.37,26.83 4481,26.83 J5/J7.47@4554.17,100 ; v1(3474.14,1685.18) 3476.67,1687.71 3476.67,1693.77 3525.37,1742.46 3668.27,1742.46 3705.69,1779.88 3849.91,1779.88 3888.32,1741.47 3935.57,1741.47 4027.1,1649.94 4053.01,1649.94 4060.87,1657.8 4060.87,1685.35 4005.81,1740.41 4005.81,1947 4081.47,2022.67 4525.92,2022.67 4601.67,1946.93 4601.67,1730.66 4615,1717.33 v1(4615.43,1717.33)
  Bottom Layer w5.3: v1(1896.53,1255.29) 1921.67,1280.44 1921.67,1590.35 1945.34,1614.02 2048.37,1614.02 2073.78,1639.43 2586.12,1639.43 2612.34,1665.64 3021.13,1665.64 3055.77,1700.29 3459.02,1700.29 v1(3474.14,1685.18) ; v1(4509.06,1235.1) 4509.06,1238.3 4518,1247.24 4518,1424 4535,1441 4579,1441 4630.24,1389.76 4670.47,1389.76 4682.41,1401.69 4682.41,1441.17 4677.03,1446.55 4677.03,1499.12 4640.64,1535.51 4640.64,1587.78 4615.43,1612.99 v1(4615.43,1717.33)
AM261_SPI2_CS0: U29.8 U34.M1 | length 923.9
  Top Layer w5.3: U29.8@3533.87,1488.24 3533.87,1471.67 3652.06,1353.47 3652.06,1216.17 3716.96,1151.27 3716.96,1147.35 3744.55,1119.76 3744.61,1119.76 3746.53,1117.83 3848.59,1117.83 v1(3849.69,1116.73) ; v1@3948.5,963.79 v1(3949.03,963.79) 3958.02,963.79 4010.34,1016.11 U34.M1@4094.49,1016.11
  SIG 1 w4.75: v1(3849.69,1116.73) 3849.69,1113.57 3926.14,1037.12 3926.14,986.69 v1(3949.03,963.79)
AM261_SPI2_CS1: J6/J8.59 U34.A18 | length 2028.6
  Top Layer w5.3: J6/J8.59@4054.17,1900 4099.09,1855.08 4183.65,1855.08 4200.16,1871.6 4200.16,1918.59 4200.16,1920.88 4234.07,1954.79 4236.37,1954.79 4471.38,1954.79 4504.17,1922 4504.17,1877.15 4526.29,1855.03 4671.7,1855.03 4700.44,1883.78 4700.44,1927.07 4702.28,1928.91 4724.98,1951.61 4728.44,1955.07 4889.55,1955.07 4893.01,1951.61 4951.78,1892.84 4951.78,1875.41 4951.78,1700.77 4891.61,1640.6 4891.61,1526.34 4882.53,1517.27 4758.56,1517.27 4749.17,1507.88 4748.75,1507.88 4739.5,1498.64 4738.08,1497.21 4731.31,1490.44 4731.31,1485.77 4731.31,1450.21 4663.43,1382.33 4596.73,1382.33 4571.57,1357.18 4529.52,1315.13 4529.52,1313.55 U34.A18@4529.52,1297.6
AM261_SPI2_D0: J6/J8.55 U34.A16 | length 1454.4
  Top Layer w5.3: J6/J8.55@4454.17,1900 4509.44,1844.73 4675.96,1844.73 4679.89,1848.66 4710.74,1879.51 4710.74,1883.55 4710.74,1922.81 4732.71,1944.77 4885.28,1944.77 4941.18,1888.87 4941.18,1705.16 4901.57,1665.55 4863.73,1665.55 4768.35,1570.17 4740.34,1570.17 4676.59,1506.42 4646.33,1506.42 4627.22,1487.31 4627.22,1449.11 4611.14,1433.03 4585.13,1433.03 4500.52,1348.43 4478.34,1326.25 U34.A16@4478.34,1297.6
AM261_SPI2_D1: J6/J8.54 U34.B18 | length 1379.3
  Top Layer w3.94: U34.B18@4529.52,1272.01 4542.32,1284.81 4542.32,1312.68 4555.22,1325.58
  Top Layer w5.3: J6/J8.54@4554.17,1900 4616.08,1961.91 4720.72,1961.91 4724.18,1965.37 4893.81,1965.37 4897.28,1961.91 4962.38,1896.8 4962.38,1695.84 4903.35,1636.8 4903.35,1523.52 4886.66,1506.83 4762.69,1506.83 4743.36,1487.51 4743.36,1447.28 4666.63,1370.55 4600.19,1370.55 4555.22,1325.58
AM261_TCK: R29.1 R376.2 U34.D4 | length 3965.7
  Top Layer w3.94: v1(4165.31,1235.75) U34.D4@4171.26,1220.83
  Top Layer w5.3: R29.1@1537.64,973.08 1572.05,973.08 v1(1572.35,973.37)
  Bottom Layer w3.94: v1(4165.31,1235.75) 4186.1,1235.75 4201.72,1251.37
  Bottom Layer w5.3: R376.2@1537.64,973.08 1572.05,973.08 v1(1572.35,973.37) 1572.35,948.69 1563.6,939.94 1482.5,939.94 1463.47,920.91 1463.47,864.26 1594.71,733.03 2050.15,733.03 2117.92,800.8 2406.67,800.8 2443.25,764.22 2548.88,764.22 2594.08,809.42 2639.05,809.42 2639.61,809.98 2648.3,809.98 2725.87,887.55 2725.87,1063.62 2731.98,1069.73 2731.98,1158.14 2707.9,1182.22 2707.9,1287.34 2838.71,1418.16 3001.95,1418.16 3008.2,1411.91 3068.47,1411.91 3112.56,1456 ; 3112.56,1456.04 3115.42,1458.9 3115.42,1508.72 3153.57,1546.87 3245.99,1546.87 3269.21,1523.65 3269.21,1476.14 3329,1416.35 3579.02,1416.35 3626.42,1368.95 3783.94,1368.95 3795.22,1380.23 3924.04,1380.23 4037.8,1266.47 4109.31,1266.47 4118.4,1275.57 4193.29,1275.57 4201.72,1267.14 4201.72,1251.37
AM261_TCK_R: R29.2 U11.7 | length 90.4
  Top Layer w5.3: U11.7@1408.5,993.59 1442.59,993.59 1463.1,973.08 R29.2@1490.39,973.08
AM261_TCK_XDS: R8.1 U11.2 | length 889
  Top Layer w5.3: R8.1@500,1282.12 500,1253.53 522.58,1230.95 622.7,1230.95 912.63,941.02 1136.4,941.02 1146.81,951.42 1146.81,981.65 1158.74,993.59 U11.2@1191.5,993.59
AM261_TDI: R27.1 R377.2 U34.C5 | length 4158.3
  Top Layer w5.3: R27.1@1536.5,1177.74 v1(1573.23,1177.74) ; v1(4184.27,1255.87) 4187.4,1255.87 U34.C5@4196.85,1246.42
  Bottom Layer w5.3: R377.2@1536.5,1177.74 v1(1573.23,1177.74) 1573.23,1154.13 1563.8,1144.7 1477.28,1144.7 1447.95,1115.38 1447.95,858.56 1596.94,709.57 2070.01,709.57 2104.1,743.66 2357.16,743.66 2416.79,684.03 2471.85,684.03 2471.92,683.96 2525.47,683.96 2525.54,684.03 2531.42,684.03 2605.31,757.93 2645.43,757.93 2737.67,850.16 2737.67,1057.51 2744.71,1064.56 2744.71,1160.4 2718.97,1186.14 2718.97,1283.41 2812.94,1377.37 3053.17,1377.37 3127.2,1451.4 3127.2,1505.2 3155.57,1533.57 3238.76,1533.57 3258.91,1513.41 3258.91,1470.5 3323.2,1406.21 3324.57,1406.21 3324.73,1406.05 3572.4,1406.05 3619.8,1358.65 3788.52,1358.65 3806.03,1341.15 3938.76,1341.15 4024.03,1255.87 v1(4184.27,1255.87)
AM261_TDI_R: R27.2 U13.2 | length 84.3
  Top Layer w5.3: U13.2@1408.27,1169.73 1453.12,1169.73 1461.13,1177.74 R27.2@1489.25,1177.74
AM261_TDI_XDS: R11.1 U13.7 | length 740
  Top Layer w5.3: R11.1@549.89,1282.74 608.14,1282.74 732.38,1158.5 925.95,1158.5 957,1189.55 1020.82,1189.55 1051.8,1220.52 1111.51,1220.52 1162.3,1169.73 U13.7@1191.73,1169.73
AM261_TDO: R30.2 R327.2 U13.3 | length 3813.1
  Top Layer w5.3: U13.3@1408.27,1219.73 1457.35,1219.73 v1(1458.14,1218.93) 1458.14,1238.21 1471.03,1251.09 R30.2@1500.04,1251.09
  Bottom Layer w5.3: v1(1458.14,1218.93) 1432.69,1193.48 1432.69,851.65 1588.56,695.78 2082.89,695.78 2115.99,728.89 2354.71,728.89 2410.56,673.04 2537.48,673.04 2611,746.55 2651.22,746.55 2747.97,843.29 2747.97,1048.52 2761.85,1062.4 2761.85,1216.79 2761.76,1216.88 2761.76,1309.67 2761.85,1309.76 2761.85,1310.18 2816.85,1365.19 3064.28,1365.19 3144.83,1445.74 3144.83,1500.11 3166.91,1522.19 3229.18,1522.19 3247.47,1503.9 3247.47,1461.18 3341.09,1367.56 3399.41,1367.56 3420.19,1388.34 3572.01,1388.34 3640.35,1320 3792.57,1320 3813.1,1299.47 3847.7,1299.47 3850.89,1302.66 3850.89,1304.63 3858.08,1311.83 R327.2@3860.05,1311.83
AM261_TDO_R: R327.1 U34.E5 | length 364.7
  Top Layer w5.3: v1(4194.53,1223.15) 4196.85,1220.83 U34.E5@4196.85,1195.24
  Bottom Layer w5.3: R327.1@3899.42,1311.83 3950.47,1311.83 4017.39,1244.9 4131.69,1244.9 4158.21,1218.38 4189.76,1218.38 v1(4194.53,1223.15)
AM261_TDO_XDS: U13.6 U63.37 | length 900
  Top Layer w5.3: v1(480.59,1413.28) 518.47,1413.28 731.61,1200.14 861.94,1200.14 862.36,1200.55 878.53,1200.55 878.95,1200.14 927.07,1200.14 947.45,1220.52 1018.01,1220.52 1042.72,1245.24 1117.14,1245.24 v1(1141.85,1220.52) 1142.65,1219.73 U13.6@1191.73,1219.73
  Bottom Layer w5.3: U63.37@464.4,1477.52 464.4,1429.47 v1(480.59,1413.28)
AM261_TEMPCAL: U34.W3
AM261_TMS: R28.1 R375.2 U34.D6 | length 3649.5
  Top Layer w5.3: R28.1@1537.64,904.65 1570.52,904.65 v1(1572.35,902.82) ; v1(4217.57,1235.19) 4222.44,1230.33 U34.D6@4222.44,1220.83
  Bottom Layer w5.3: R375.2@1537.64,904.65 1570.52,904.65 v1(1572.35,902.82) 1726.63,748.54 2039.72,748.54 2102.72,811.54 2411.55,811.54 2448.58,774.52 2544.13,774.52 2589.92,820.31 2643.14,820.31 2685,862.17 2685,1279.01 2834.74,1428.76 3006.53,1428.76 3013.08,1422.21 3064.21,1422.21 3102.26,1460.26 3102.26,1517.42 3147.47,1562.63 3244.81,1562.63 3279.51,1527.92 3279.51,1481.29 3333.92,1426.88 3585.57,1426.88 3597.24,1415.21 3597.48,1415.21 3633.44,1379.25 3779.25,1379.25 3790.83,1390.83 3930.51,1390.83 4044.26,1277.07 4098.97,1277.07 4110.09,1288.2 4199.36,1288.2 4217.57,1270 v1(4217.57,1235.19)
AM261_TMS_R: R28.2 U11.6 | length 109.2
  Top Layer w5.3: U11.6@1408.5,943.59 1470.58,943.59 1490.39,923.77 R28.2@1490.39,904.65
AM261_TMS_XDS: R6.1 U11.3 | length 920.9
  Top Layer w5.3: R6.1@448.79,1282.12 448.79,1244.13 488.82,1204.11 615.24,1204.11 894.69,924.66 1142.65,924.66 1161.58,943.59 U11.3@1191.5,943.59
AM261_UART0_RXD: R4.1 U34.A8 | length 4959.3
  Top Layer w5.3: R4.1@264.01,1960.51 264.01,1985.37 291.3,2012.66 322.69,2012.66 355.65,1979.7 500.79,1979.7 549.98,1930.51 1230.36,1930.51 1426.32,1734.55 1782.16,1734.55 1896.32,1620.38 v1(1896.32,1562.73) ; v1(4261.48,1424.05) 4261.9,1424.05 4273.62,1412.33 U34.A8@4273.62,1297.6
  SIG 1 w4.75: v1(1896.32,1562.73) 1897.97,1564.38 2478.32,1564.38 v1(2631,1411.69)
  Bottom Layer w5.3: v1(2631,1411.69) 2699.88,1411.69 2781,1492.81 2933.79,1492.81 2987.85,1546.87 2998.94,1546.87 3026.03,1573.97 3099.58,1573.97 3150.44,1624.82 3253.57,1624.82 3404.75,1473.63 3563.9,1473.63 3592.19,1501.92 3614.49,1501.92 3623.6,1492.81 3669.41,1492.81 3677.19,1485.03 3729.29,1485.03 3777.6,1533.34 3855.04,1533.34 3868.58,1546.87 3868.58,1644.89 3913.71,1690.02 4045.89,1690.02 4067.74,1668.18 4167.24,1668.18 4190.45,1644.96 4190.45,1495.07 v1(4261.48,1424.05)
AM261_UART0_RXD_R: R4.2 U3.2 | length 64.2
  Top Layer w5.3: U3.2@264.01,1849.08 R4.2@264.01,1913.27
AM261_UART0_RXD_XDS: R412.1 U3.7 | length 135.9
  Top Layer w5.3: U3.7@264.01,1632.55 264.01,1690.52 v1(264.06,1690.56)
  Bottom Layer w5.3: v1(264.06,1690.56) 304.11,1690.56 314.01,1680.67 R412.1@314.01,1656.86
AM261_UART0_TXD: R138.1 U3.3 | length 5510.4
  Top Layer w5.3: U3.3@214.01,1849.08 214.01,1956.12 281.15,2023.26 337.97,2023.26 367.96,1993.28 505.85,1993.28 558.01,1941.11 1234.32,1941.11 1430.58,1744.85 1809.01,1744.85 1941.42,1612.44 1941.42,1612.36 1950.36,1603.42 1950.44,1603.42 v1(1959.64,1594.22) ; R138.1@4269.11,1506.95 4269.11,1523.57 v1(4300.98,1555.44)
  Bottom Layer w5.3: v1(1959.64,1594.22) 2069.36,1594.22 2093.4,1618.26 2579.52,1618.26 2616.6,1655.34 3036.55,1655.34 3071.2,1689.99 3366.43,1689.99 3442.92,1613.5 3501.08,1613.5 3521.29,1593.29 3637.7,1593.29 3646.86,1584.13 3704.31,1584.13 3742.39,1622.21 3742.39,1716.39 3756,1730 3756,1754.95 3738.35,1772.6 3684.76,1772.6 3671.68,1759.52 3636.52,1759.52 3610.61,1785.43 3610.61,1926.12 3646.72,1962.24 3738.39,1962.24 3809.59,1891.03 3838.08,1891.03 3897.15,1951.64 4078.21,1951.64 4098.18,1931.67 4098.18,1855.17 4109.31,1844.03 4109.31,1784.16 4134.5,1758.96 4179.72,1758.96 4263.17,1675.51 4263.17,1579.79 4287.52,1555.44 v1(4300.98,1555.44)
AM261_UART0_TXD_XDS: R413.1 U3.6 | length 132.8
  Top Layer w5.3: v1(213.57,1689.72) 214.01,1689.28 U3.6@214.01,1632.55
  Bottom Layer w5.3: v1(213.57,1689.72) 213.57,1670.35 227.05,1656.86 R413.1@264.01,1656.86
